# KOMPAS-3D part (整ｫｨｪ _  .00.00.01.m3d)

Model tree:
1. Эскиз:1
2. Операция выдавливания:1
     Расстояние 1 = 70; Расстояние 2 = 36
3. Эскиз:2
4. Операция выдавливания:2
     Расстояние 1 = 69; Расстояние 2 = 36
5. Эскиз:3
6. Вырезать элемент выдавливания:1
     Расстояние 1 = 1
7. Эскиз:4
8. Операция выдавливания:3
     Расстояние 1 = 70; Расстояние 2 = 36
9. Эскиз:5
10. Операция выдавливания:4
     Расстояние 1 = 69; Расстояние 2 = 36
11. Эскиз:6
12. Вырезать элемент выдавливания:2
     Расстояние 2 = 1; Расстояние 1 = 1
13. Эскиз:7
14. Операция выдавливания:5
     Расстояние 1 = 70; Расстояние 2 = 36
15. Скругление:1
     Радиус = 1
16. Скругление:2  (labels: Полиэтилен ВД  ГОСТ 16337-77)
     Радиус = 5

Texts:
  (Колесо от рохли 70х80)
  Полиэтилен ВД  ГОСТ 16337-77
